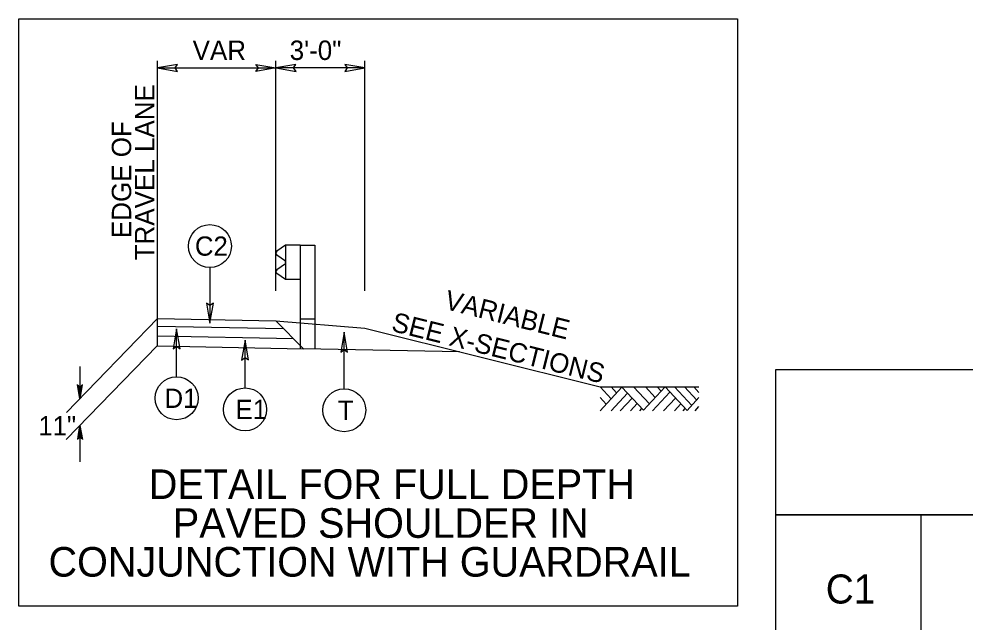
# Model space of a CAD drawing. Extents: x 1901984 to 1902132, y 194049 to 194156.
# Drawn here: x 1902056.68 to 1902088.64, y 194104.06 to 194124.42 of the extents above; entities that cross this region are included whole.
import ezdxf

# ---------------------------------------------------------------- set-up
doc = ezdxf.new("R2010")
doc.units = 0
for name, color, linetype in [('Old_Level_1', 7, 'Continuous'), ('Old_Level_11', 7, 'Continuous'), ('Old_Level_19', 7, 'Continuous'), ('Old_Level_20', 7, 'Continuous'), ('Old_Level_21', 7, 'Continuous'), ('Typical Guardrail CELL', 7, 'Continuous')]:
    doc.layers.add(name, color=color, linetype=linetype)

msp = doc.modelspace()

# ---------------------------------------------------------------- linework, layer by layer
at = {"layer": 'Old_Level_1'}
for p, q in [((1902061.364, 194113.386), (1902061.364, 194123.012)), ((1902065.364, 194115.239), (1902065.364, 194123.012)), ((1902068.364, 194115.239), (1902068.364, 194123.012)), ((1902061.364, 194122.766), (1902065.364, 194122.766)), ((1902068.364, 194122.766), (1902065.364, 194122.766)), ((1902065.364, 194115.239), (1902065.364, 194120.851)), ((1902068.364, 194115.239), (1902068.364, 194120.851)), ((1902061.364, 194114.303), (1902058.296, 194111.133)), ((1902061.366, 194114.303), (1902065.364, 194114.223)), ((1902061.361, 194114.053), (1902065.62, 194113.968)), ((1902065.364, 194114.223), (1902068.364, 194113.983)), ((1902065.364, 194114.223), (1902066.3, 194113.288)), ((1902068.364, 194113.983), (1902076.311, 194111.997)), ((1902061.354, 194113.72), (1902065.96, 194113.628)), ((1902061.348, 194113.387), (1902058.28, 194110.217)), ((1902061.348, 194113.387), (1902066.3, 194113.288)), ((1902071.568, 194113.182), (1902066.3, 194113.288)), ((1902058.745, 194112.686), (1902058.745, 194111.597)), ((1902058.745, 194111.597), (1902058.661, 194112.074)), ((1902058.745, 194111.597), (1902058.673, 194112.065)), ((1902058.685, 194112.056), (1902058.745, 194111.597)), ((1902058.745, 194111.597), (1902058.697, 194112.048)), ((1902058.709, 194112.039), (1902058.745, 194111.597)), ((1902058.745, 194111.597), (1902058.721, 194112.03)), ((1902058.733, 194112.021), (1902058.745, 194111.597)), ((1902058.745, 194111.597), (1902058.83, 194112.074)), ((1902058.818, 194112.065), (1902058.745, 194111.597)), ((1902058.745, 194111.597), (1902058.805, 194112.056)), ((1902058.793, 194112.048), (1902058.745, 194111.597)), ((1902058.745, 194111.597), (1902058.781, 194112.039)), ((1902058.769, 194112.03), (1902058.745, 194111.597)), ((1902058.745, 194111.597), (1902058.757, 194112.021)), ((1902058.745, 194112.012), (1902058.745, 194111.597)), ((1902058.745, 194110.698), (1902058.661, 194110.221)), ((1902058.673, 194110.23), (1902058.745, 194110.698)), ((1902058.745, 194110.698), (1902058.685, 194110.239)), ((1902058.697, 194110.248), (1902058.745, 194110.698)), ((1902058.745, 194110.698), (1902058.709, 194110.256)), ((1902058.721, 194110.265), (1902058.745, 194110.698)), ((1902058.745, 194110.698), (1902058.733, 194110.274)), ((1902058.745, 194110.698), (1902058.83, 194110.221)), ((1902058.757, 194110.274), (1902058.745, 194110.698)), ((1902058.745, 194110.698), (1902058.769, 194110.265)), ((1902058.781, 194110.256), (1902058.745, 194110.698)), ((1902058.745, 194110.698), (1902058.793, 194110.248)), ((1902058.805, 194110.239), (1902058.745, 194110.698)), ((1902058.745, 194110.698), (1902058.818, 194110.23)), ((1902058.745, 194110.698), (1902058.745, 194109.473))]:
    msp.add_line(p, q, dxfattribs=at)
msp.add_lwpolyline([(1902076.311, 194111.997), (1902079.653, 194111.997)], dxfattribs=at)
at = {"layer": 'Old_Level_11'}
for p, q in [((1902063.134, 194116.027), (1902063.134, 194114.153)), ((1902062.011, 194112.339), (1902062.011, 194113.958)), ((1902067.671, 194111.933), (1902067.671, 194113.845)), ((1902064.32, 194111.962), (1902064.32, 194113.581)), ((1902076.311, 194111.997), (1902076.686, 194111.594)), ((1902076.311, 194111.192), (1902077.053, 194111.989)), ((1902076.685, 194111.192), (1902077.239, 194111.788)), ((1902076.686, 194111.997), (1902076.873, 194111.796)), ((1902077.053, 194111.989), (1902077.777, 194111.21)), ((1902077.444, 194111.997), (1902077.977, 194111.424)), ((1902077.777, 194111.21), (1902078.508, 194111.996)), ((1902077.842, 194111.997), (1902078.175, 194111.638)), ((1902078.087, 194111.192), (1902078.673, 194111.82)), ((1902078.244, 194111.997), (1902078.377, 194111.854)), ((1902078.508, 194111.996), (1902079.249, 194111.2)), ((1902078.83, 194111.997), (1902079.41, 194111.374)), ((1902079.163, 194111.997), (1902079.577, 194111.553)), ((1902079.483, 194111.997), (1902079.653, 194111.814)), ((1902076.311, 194111.635), (1902076.517, 194111.413)), ((1902076.994, 194111.192), (1902077.395, 194111.621)), ((1902077.341, 194111.192), (1902077.568, 194111.435)), ((1902078.457, 194111.192), (1902078.857, 194111.621)), ((1902078.823, 194111.192), (1902079.04, 194111.425)), ((1902079.249, 194111.2), (1902079.653, 194111.635)), ((1902077.652, 194111.192), (1902077.723, 194111.268)), ((1902079.118, 194111.192), (1902079.187, 194111.266)), ((1902079.519, 194111.192), (1902079.653, 194111.335))]:
    msp.add_line(p, q, dxfattribs=at)
for points in [[(1902056.683, 194124.422), (1902080.956, 194124.422), (1902080.956, 194104.591), (1902056.683, 194104.591)], [(1902067.689, 194122.65), (1902068.364, 194122.766), (1902067.686, 194122.886), (1902067.772, 194122.766)], [(1902062.039, 194122.882), (1902061.364, 194122.766), (1902062.043, 194122.646), (1902061.957, 194122.766)], [(1902064.69, 194122.882), (1902065.365, 194122.766), (1902064.686, 194122.646), (1902064.772, 194122.766)], [(1902066.039, 194122.882), (1902065.364, 194122.766), (1902066.043, 194122.646), (1902065.957, 194122.766)], [(1902063.018, 194114.824), (1902063.134, 194114.153), (1902063.253, 194114.828), (1902063.134, 194114.742)], [(1902062.126, 194113.286), (1902062.011, 194113.958), (1902061.891, 194113.283), (1902062.011, 194113.368)], [(1902067.787, 194113.173), (1902067.671, 194113.845), (1902067.552, 194113.169), (1902067.671, 194113.255)], [(1902064.436, 194112.91), (1902064.32, 194113.581), (1902064.201, 194112.906), (1902064.32, 194112.992)]]:
    msp.add_lwpolyline(points, close=True, dxfattribs=at)
for centre in [(1902063.134, 194116.752), (1902062.011, 194111.613), (1902064.32, 194111.237), (1902067.671, 194111.208)]:
    msp.add_circle(centre, 0.725, dxfattribs=at)
at = {"layer": 'Old_Level_19'}
msp.add_lwpolyline([(1902082.253, 194112.582), (1902130.254, 194112.582), (1902130.254, 194107.673), (1902082.253, 194107.673)], close=True, dxfattribs=at)
msp.add_lwpolyline([(1902087.162, 194102.764), (1902082.253, 194102.764), (1902082.253, 194107.673), (1902130.253, 194107.673), (1902130.253, 194102.764), (1902087.162, 194102.764), (1902087.162, 194107.673)], dxfattribs=at)
at = {"layer": 'Typical Guardrail CELL'}
for p, q in [((1902065.687, 194116.779), (1902065.398, 194116.576)), ((1902066.185, 194116.779), (1902065.687, 194116.779)), ((1902065.687, 194116.779), (1902065.687, 194115.619)), ((1902066.185, 194116.779), (1902066.185, 194114.293)), ((1902066.185, 194116.779), (1902066.682, 194116.779)), ((1902066.682, 194116.779), (1902066.682, 194114.293)), ((1902065.687, 194116.245), (1902065.398, 194116.448)), ((1902065.687, 194116.199), (1902065.687, 194116.245)), ((1902065.687, 194116.199), (1902065.687, 194116.152)), ((1902065.687, 194116.152), (1902065.398, 194115.949)), ((1902065.687, 194115.619), (1902065.398, 194115.822)), ((1902066.185, 194115.619), (1902065.687, 194115.619)), ((1902066.185, 194114.293), (1902066.682, 194114.293)), ((1902066.185, 194114.293), (1902066.185, 194113.285)), ((1902066.682, 194114.293), (1902066.682, 194113.285))]:
    msp.add_line(p, q, dxfattribs=at)
for centre, start, end in [((1902065.442, 194116.512), 125.003, 235.0112), ((1902065.442, 194115.885), 125.0059, 235.0366)]:
    msp.add_arc(centre, 0.0776, start, end, dxfattribs=at)

# ---------------------------------------------------------------- texts
at = {"layer": 'Old_Level_1'}
for s, rotation, p in [('VAR', 360, (1902062.551, 194123.036)), ('3\'-0"', 360, (1902065.829, 194123.036)), ('TRAVEL LANE', 90, (1902061.257, 194116.271)), ('EDGE OF', 90, (1902060.476, 194117.022)), ('VARIABLE', 345.9638, (1902071.022, 194114.637)), ('SEE X-SECTIONS', 345.9638, (1902069.231, 194113.893))]:
    msp.add_text(s, height=0.656, rotation=rotation, dxfattribs=at).set_placement(p)
at = {"layer": 'Old_Level_11'}
for s, p in [('DETAIL FOR FULL DEPTH', (1902061.071, 194108.213)), ('PAVED SHOULDER IN', (1902061.883, 194106.902)), ('CONJUNCTION WITH GUARDRAIL', (1902057.683, 194105.591))]:
    msp.add_text(s, height=1, dxfattribs=at).set_placement(p)
at = {"layer": 'Old_Level_20'}
for s, height, p in [('C2', 0.6491, (1902062.629, 194116.428)), ('T', 0.649, (1902067.458, 194110.884))]:
    msp.add_text(s, height=height, rotation=360, dxfattribs=at).set_placement(p)
for s, p in [('D1', (1902061.603, 194111.289)), ('E1', (1902064.001, 194110.912)), ('11"', (1902057.341, 194110.362))]:
    msp.add_text(s, height=0.6491, dxfattribs=at).set_placement(p)
at = {"layer": 'Old_Level_21'}
msp.add_text('C1', height=0.98, dxfattribs=at).set_placement((1902083.935, 194104.684))

doc.saveas('drawing.dxf')
